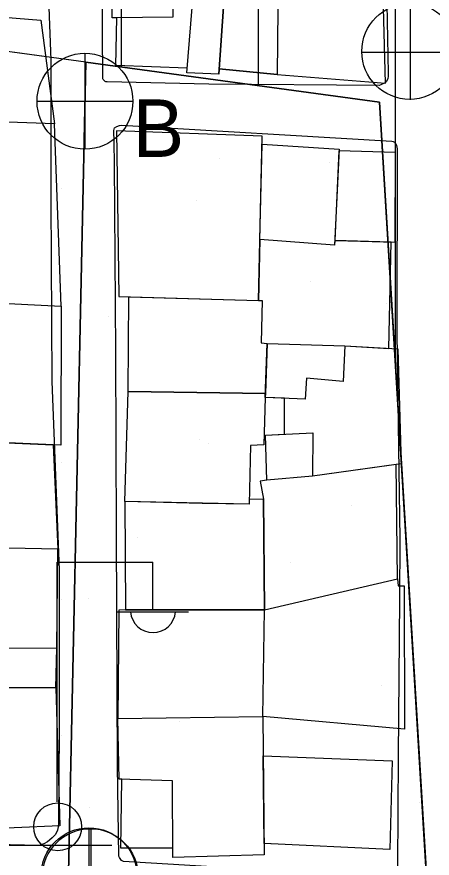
# Model space of a CAD drawing. Extents: x 417997 to 421451, y 4451742 to 4455216.
# Drawn here: x 419258.5 to 419288.8, y 4453119.4 to 4453180.8 of the extents above; entities that cross this region are included whole.
import ezdxf

# ---------------------------------------------------------------- set-up
doc = ezdxf.new("R2010")
doc.units = 0
for name, color, linetype in [('ADA', 7, 'Continuous'), ('B_Mesken', 7, 'Continuous'), ('B_Teras', 7, 'Continuous'), ('Default', 7, 'Continuous'), ('LJ_SEMBOL', 7, 'Continuous'), ('PL_AYA_PARK_DINLENME', 7, 'Continuous'), ('PL_KON_MEV_350', 7, 'Continuous'), ('PL_SAY_DINI_TESIS', 7, 'Continuous'), ('S_Elektrik_Diregi', 7, 'Continuous'), ('S_Rogar_Kapagi', 7, 'Continuous'), ('S_Rogar_Kapagi_Buski', 7, 'Continuous'), ('TR_DINITESIS', 7, 'Continuous'), ('TR_ORTAYOGUNKONUT', 7, 'Continuous'), ('TR_PARKALANI', 7, 'Continuous'), ('Yol_Sose', 7, 'Continuous')]:
    doc.layers.add(name, color=color, linetype=linetype)

# ---------------------------------------------------------------- blocks, each defined once
blk = doc.blocks.new('POINT_DISPLAY')
at = {"layer": 'Default'}
blk.add_line((0, 0), (0, 0), dxfattribs=at)

msp = doc.modelspace()

# ---------------------------------------------------------------- linework, layer by layer
at = {"layer": 'ADA'}
for p, q in [((419263.499, 4453177.524), (419222.131, 4453183.165)), ((419263.499, 4453177.524), (419222.131, 4453183.165)), ((419263.499, 4453177.524), (419262.248, 4453118.305)), ((419263.499, 4453177.524), (419262.248, 4453118.305)), ((419284.956, 4453174.598), (419263.499, 4453177.524)), ((419284.956, 4453174.598), (419263.499, 4453177.524)), ((419288.411, 4453117.789), (419284.956, 4453174.598)), ((419288.411, 4453117.789), (419284.956, 4453174.598))]:
    msp.add_line(p, q, dxfattribs=at)
at = {"layer": 'B_Mesken'}
for points in [[(419265.374, 4453184.241), (419269.88, 4453184.263), (419273.726, 4453184.043), (419273.25, 4453177.039), (419273.224, 4453176.649), (419270.895, 4453176.75), (419270.921, 4453177.081), (419265.689, 4453177.287), (419265.776, 4453180.762), (419265.428, 4453180.757)], [(419277.55, 4453183.83), (419273.726, 4453184.043), (419273.25, 4453177.039), (419277.491, 4453176.638), (419285.399, 4453175.992), (419285.208, 4453183.366)], [(419247.967, 4453173.539), (419248.017, 4453179.656), (419248.763, 4453181.514), (419260.213, 4453180.588), (419261.208, 4453173.024), (419251.746, 4453173.37)], [(419251.746, 4453173.37), (419251.371, 4453163.802), (419251.499, 4453160.206), (419261.697, 4453159.699), (419261.208, 4453173.024)], [(419265.75, 4453172.507), (419265.922, 4453160.401), (419276.114, 4453160.113), (419276.401, 4453172.132)], [(419276.387, 4453171.539), (419282.008, 4453171.172), (419281.681, 4453164.152), (419276.221, 4453164.577)], [(419286.142, 4453170.938), (419282.002, 4453171.045), (419281.698, 4453164.509), (419283.563, 4453164.459), (419286.104, 4453164.373)], [(419285.642, 4453156.621), (419285.818, 4453164.383), (419281.698, 4453164.509), (419281.681, 4453164.152), (419276.221, 4453164.577), (419276.114, 4453160.113), (419276.385, 4453160.109), (419276.317, 4453157.035), (419276.75, 4453156.975), (419282.433, 4453156.798)], [(419276.628, 4453153.324), (419266.59, 4453153.47), (419266.636, 4453160.381), (419276.114, 4453160.113), (419276.385, 4453160.109), (419276.317, 4453157.035), (419276.75, 4453156.975)], [(419251.687, 4453149.982), (419251.499, 4453160.206), (419261.697, 4453159.699), (419261.669, 4453149.559)], [(419282.433, 4453156.798), (419286.304, 4453156.584), (419286.535, 4453148.189), (419280.065, 4453147.293), (419276.718, 4453146.989), (419276.641, 4453150.281), (419278.031, 4453150.35), (419278.023, 4453152.98), (419276.619, 4453153.042), (419276.75, 4453156.975)], [(419266.36, 4453145.425), (419266.59, 4453153.47), (419276.628, 4453153.324), (419276.619, 4453153.042), (419276.51, 4453149.567), (419275.539, 4453149.533), (419275.433, 4453145.227), (419272.01, 4453145.286)], [(419253.075, 4453142.117), (419252.263, 4453142.1), (419252.707, 4453149.939), (419261.126, 4453149.582), (419261.468, 4453141.956)], [(419276.718, 4453146.989), (419276.237, 4453146.925), (419276.497, 4453145.596), (419276.567, 4453137.528), (419286.287, 4453139.788), (419286.176, 4453148.14), (419280.065, 4453147.293), (419276.718, 4453146.989)], [(419266.36, 4453145.425), (419266.405, 4453137.52), (419276.567, 4453137.528), (419276.497, 4453145.596), (419275.442, 4453145.579), (419275.433, 4453145.227)], [(419253.075, 4453142.117), (419253.068, 4453137.927), (419251.526, 4453137.92), (419251.645, 4453134.756), (419251.637, 4453133.756), (419251.612, 4453131.838), (419261.305, 4453131.823), (419261.382, 4453134.714), (419261.468, 4453141.956)], [(419286.287, 4453139.788), (419286.337, 4453139.273), (419286.77, 4453139.267), (419286.794, 4453128.791), (419276.437, 4453129.724), (419276.567, 4453137.528)], [(419276.437, 4453129.724), (419276.567, 4453137.528), (419266.405, 4453137.52), (419265.917, 4453137.499), (419265.834, 4453129.59)], [(419261.305, 4453131.823), (419261.602, 4453121.738), (419251.565, 4453121.309), (419251.612, 4453131.838)], [(419266.059, 4453120.11), (419266.127, 4453125.151), (419265.933, 4453125.157), (419265.834, 4453129.59), (419276.437, 4453129.724), (419276.544, 4453119.617), (419269.862, 4453119.432), (419269.858, 4453120.108)], [(419276.467, 4453126.843), (419285.894, 4453126.48), (419285.706, 4453120.012), (419276.535, 4453120.457)]]:
    msp.add_lwpolyline(points, close=True, dxfattribs=at)
at = {"layer": 'B_Teras'}
for points in [[(419265.428, 4453180.757), (419265.374, 4453184.241), (419269.88, 4453184.263), (419269.851, 4453180.812)], [(419270.895, 4453176.75), (419271.372, 4453182.73), (419269.867, 4453182.739), (419269.88, 4453184.263), (419273.726, 4453184.043), (419273.224, 4453176.649)], [(419273.224, 4453176.649), (419273.726, 4453184.043), (419277.55, 4453183.83), (419277.491, 4453176.638), (419273.25, 4453177.039)], [(419276.619, 4453153.042), (419276.75, 4453156.975), (419282.433, 4453156.798), (419282.3, 4453154.211), (419279.627, 4453154.447), (419279.519, 4453152.913)], [(419276.718, 4453146.989), (419276.641, 4453150.281), (419280.091, 4453150.451), (419280.065, 4453147.293)], [(419251.637, 4453133.756), (419251.645, 4453134.756), (419261.382, 4453134.714), (419261.305, 4453131.823), (419251.612, 4453131.838)], [(419265.933, 4453125.157), (419265.834, 4453129.59), (419276.437, 4453129.724), (419276.544, 4453119.617), (419269.862, 4453119.432), (419269.827, 4453125.026)]]:
    msp.add_lwpolyline(points, close=True, dxfattribs=at)
at = {"layer": 'LJ_SEMBOL'}
msp.add_line((419265.405, 4453120.303), (419218.744, 4453120.3), dxfattribs=at)
msp.add_line((419265.405, 4453120.303), (419218.744, 4453120.3), dxfattribs=at)
at = {"layer": 'PL_AYA_PARK_DINLENME'}
msp.add_lwpolyline([(419262.248, 4453118.305), (419263.499, 4453177.524), (419284.956, 4453174.598), (419288.411, 4453117.789)], close=True, dxfattribs=at)
msp.add_lwpolyline([(419262.248, 4453118.305), (419263.499, 4453177.524), (419284.956, 4453174.598), (419288.411, 4453117.789)], close=True, dxfattribs=at)
at = {"layer": 'PL_KON_MEV_350'}
msp.add_lwpolyline([(419305.225, 4453063.565), (419284.03, 4453063.124), (419279.99, 4453063.095), (419275.951, 4453063.174), (419271.915, 4453063.362), (419267.886, 4453063.658), (419263.866, 4453064.063), (419259.859, 4453064.577), (419255.867, 4453065.197), (419251.893, 4453065.925), (419214.319, 4453073.334), (419206.12, 4453085.138), (419211.699, 4453119.301), (419262.248, 4453118.305), (419288.411, 4453117.789), (419284.956, 4453174.598), (419263.499, 4453177.524), (419222.131, 4453183.165), (419227.022, 4453213.113), (419238.503, 4453221.37), (419324.529, 4453207.319)], dxfattribs=at)
at = {"layer": 'PL_SAY_DINI_TESIS'}
msp.add_lwpolyline([(419226.12, 4453119.017), (419236.12, 4453118.82), (419246.12, 4453118.623), (419256.12, 4453118.426), (419262.248, 4453118.305), (419263.499, 4453177.524), (419256.12, 4453178.531), (419246.12, 4453179.894), (419239.255, 4453180.83), (419239.172, 4453154.266), (419227.381, 4453155.09), (419226.84, 4453158.31), (419218.249, 4453159.4), (419211.699, 4453119.301), (419216.12, 4453119.214), (419226.12, 4453119.017)], dxfattribs=at)
msp.add_lwpolyline([(419226.12, 4453119.017), (419236.12, 4453118.82), (419246.12, 4453118.623), (419256.12, 4453118.426), (419262.248, 4453118.305), (419263.499, 4453177.524), (419256.12, 4453178.531), (419246.12, 4453179.894), (419239.255, 4453180.83), (419239.172, 4453154.266), (419227.381, 4453155.09), (419226.84, 4453158.31), (419218.249, 4453159.4), (419211.699, 4453119.301), (419216.12, 4453119.214), (419226.12, 4453119.017)], dxfattribs=at)
at = {"layer": 'S_Elektrik_Diregi'}
for p, q in [((419261.413, 4453123.505), (419261.413, 4453141.005)), ((419261.413, 4453141.005), (419268.413, 4453141.005)), ((419268.413, 4453137.505), (419268.413, 4453141.005)), ((419265.753, 4453137.365), (419271.003, 4453137.365))]:
    msp.add_line(p, q, dxfattribs=at)
msp.add_circle((419261.449, 4453121.67), 1.75, dxfattribs=at)
msp.add_arc((419268.414, 4453137.518), 1.658, 184.83843, 355.14641, dxfattribs=at)
at = {"layer": 'S_Rogar_Kapagi'}
for p, q in [((419287.219, 4453174.782), (419287.219, 4453181.782)), ((419283.649, 4453178.247), (419290.649, 4453178.247)), ((419263.892, 4453114.504), (419263.892, 4453121.504))]:
    msp.add_line(p, q, dxfattribs=at)
for centre in [(419287.166, 4453178.31), (419263.839, 4453118.033)]:
    msp.add_circle(centre, 3.5, dxfattribs=at)
at = {"layer": 'S_Rogar_Kapagi_Buski'}
for p, q in [((419263.441, 4453178.173), (419263.441, 4453171.173)), ((419259.941, 4453174.673), (419266.941, 4453174.673)), ((419263.734, 4453121.594), (419263.734, 4453114.594))]:
    msp.add_line(p, q, dxfattribs=at)
for centre in [(419263.441, 4453174.673), (419263.734, 4453118.094)]:
    msp.add_circle(centre, 3.5, dxfattribs=at)
at = {"layer": 'TR_ORTAYOGUNKONUT'}
for p, q in [((419266.12, 4453177.167), (419266.12, 4453216.859)), ((419266.12, 4453177.167), (419266.12, 4453216.859)), ((419276.12, 4453175.803), (419276.12, 4453215.226)), ((419276.12, 4453175.803), (419276.12, 4453215.226)), ((419286.12, 4453155.472), (419286.12, 4453213.592)), ((419286.12, 4453155.472), (419286.12, 4453213.592))]:
    msp.add_line(p, q, dxfattribs=at)
at = {"layer": 'Yol_Sose'}
for points in [[(419285.567, 4453196.39), (419285.435, 4453185.62), (419285.588, 4453176.721), (419285.589, 4453176.492), (419285.564, 4453176.334), (419285.473, 4453176.111), (419285.365, 4453176.017), (419285.071, 4453175.878), (419284.934, 4453175.832), (419272.504, 4453175.932), (419265.053, 4453176.089), (419264.975, 4453176.095), (419264.926, 4453176.112), (419264.763, 4453176.252), (419264.753, 4453176.303), (419264.686, 4453186.812), (419264.652, 4453199.926), (419264.927, 4453212.529)], [(419260.886, 4453188.251), (419260.774, 4453182.195), (419260.957, 4453177.668), (419260.955, 4453167.502), (419261.016, 4453154.193)], [(419265.696, 4453156.359), (419265.597, 4453170.207), (419265.567, 4453171.552), (419265.567, 4453171.68), (419265.545, 4453172.534), (419265.567, 4453172.638), (419265.606, 4453172.727), (419265.761, 4453172.835), (419265.967, 4453172.894), (419266.116, 4453172.921), (419285.863, 4453171.764), (419285.962, 4453171.734), (419286.063, 4453171.676), (419286.202, 4453171.447), (419286.261, 4453171.195), (419286.223, 4453157.737), (419286.454, 4453142.679), (419286.428, 4453138.29), (419286.329, 4453126.862), (419286.274, 4453118.78)], [(419265.816, 4453126.096), (419265.739, 4453143.115), (419265.696, 4453156.359)], [(419261.016, 4453154.193), (419261.558, 4453140.447), (419261.568, 4453128.7), (419261.514, 4453121.957), (419261.491, 4453121.665), (419261.441, 4453121.43), (419261.284, 4453121.106), (419261.035, 4453120.853), (419260.862, 4453120.686), (419260.697, 4453120.565), (419260.447, 4453120.422), (419260.103, 4453120.308), (419252.609, 4453120.468), (419240.399, 4453121.004), (419240.025, 4453121.099), (419239.91, 4453121.152), (419239.956, 4453126.466)], [(419278.007, 4453118.435), (419266.255, 4453119.141), (419266.117, 4453119.201), (419265.959, 4453119.418), (419265.927, 4453119.53), (419265.816, 4453126.096)]]:
    msp.add_lwpolyline(points, dxfattribs=at)

# ---------------------------------------------------------------- block references
at = {"layer": 'TR_DINITESIS', "xscale": 0.1, "yscale": 0.10000000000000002}
for p in [(419261.699, 4453168.305), (419261.699, 4453168.305), (419261.699, 4453158.305), (419261.699, 4453158.305), (419261.699, 4453148.305), (419261.699, 4453148.305), (419261.699, 4453138.305), (419261.699, 4453138.305), (419261.699, 4453128.305), (419261.699, 4453128.305)]:
    msp.add_blockref('POINT_DISPLAY', p, dxfattribs=at)
at = {"layer": 'TR_PARKALANI', "xscale": 0.1, "yscale": 0.10000000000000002}
for p in [(419273.261, 4453170.503), (419273.261, 4453170.503), (419281.341, 4453170.18), (419281.341, 4453170.18), (419271.589, 4453167.41), (419271.589, 4453167.41), (419279.922, 4453161.523), (419279.922, 4453161.523), (419285.493, 4453159.881), (419285.493, 4453159.881), (419265.15, 4453158.918), (419265.15, 4453158.918), (419271.81, 4453149.938), (419271.81, 4453149.938), (419272.448, 4453149.664), (419272.448, 4453149.664), (419282.888, 4453145.109), (419282.888, 4453145.109), (419267.248, 4453142.789), (419267.248, 4453142.789), (419278.471, 4453140.959), (419278.471, 4453140.959), (419263.699, 4453138.354), (419263.699, 4453138.354), (419285.131, 4453131.979), (419285.131, 4453131.979), (419270.359, 4453129.374), (419270.359, 4453129.374), (419287.901, 4453123.468), (419287.901, 4453123.468), (419263.775, 4453123.093), (419263.775, 4453123.093), (419277.02, 4453120.394), (419277.02, 4453120.394), (419278.547, 4453120.489), (419278.547, 4453120.489)]:
    msp.add_blockref('POINT_DISPLAY', p, dxfattribs=at)

# ---------------------------------------------------------------- texts
at = {"layer": 'S_Rogar_Kapagi_Buski'}
msp.add_text('B', height=4.2, dxfattribs=at).set_placement((419266.941, 4453170.608))

doc.saveas('drawing.dxf')
